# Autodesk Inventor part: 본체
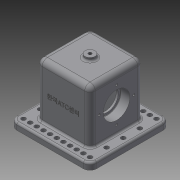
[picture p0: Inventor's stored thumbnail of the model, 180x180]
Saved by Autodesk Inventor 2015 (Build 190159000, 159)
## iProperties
Created: 2018-11
Part Number: 본체
Material: 일반
Document SubType Name: Modeling
Designer: now
Density: 1 g/cm^3
Appearance: 기본값
Author: now
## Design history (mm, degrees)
sketch "스케치1"
  geometry: L1 (-40, 40)-(40, 40); L2 (40, 40)-(40, -40); L3 (40, -40)-(-40, -40); L4 (-40, -40)-(-40, 40); L5 (-40, 40)-(40, -40); L6 (40, 40)-(-40, -40); 1 further point
  constraints: 12 end point, 2 midpoint, 2 parallel, 1 horizontal, 1 perpendicular
  dimensions: "d0" = 80 distance of L2.end L3.end; "d1" = 80 distance of L1.end L2.end
extrude "돌출1" new body sketch "스케치1" distance "d2" = 80; taper "d3" = 0 deg
fillet "모깎기1" dims "d4" = 8
sketch "스케치5"
  geometry: L1 (60, -60)-(-60, -60); L2 (-60, -60)-(-60, 60); L3 (-60, 60)-(60, 60); L4 (60, 60)-(60, -60); L5 (60, -60)-(-60, 60); L6 (-60, -60)-(60, 60); 1 further point
  constraints: 12 end point, 2 midpoint, 2 parallel, 1 horizontal, 1 perpendicular
  dimensions: "d15" = 120 distance of L3.end L1.start; "d16" = 120 distance of L2.end L3.end
extrude "돌출4" join sketch "스케치5" distance "d17" = 10; taper "d18" = 0 deg
sketch "스케치6"
  geometry: L1 (-23, -30)-(23, -30); L2 (23, -30)-(23, 30); L3 (23, 30)-(-23, 30); L4 (-23, 30)-(-23, -30); L5 (-23, -30)-(23, 30); L6 (23, -30)-(-23, 30); 1 further point
  constraints: 12 end point, 2 midpoint, 2 parallel, 1 horizontal, 1 perpendicular
  dimensions: "d19" = 46 distance of L1.start L1.end; "d20" = 60 distance of L1.end L2.end
extrude "돌출5" cut sketch "스케치6" distance "d21" = 80; taper "d22" = 0 deg
sketch "스케치8"
  geometry: L1 (80, 64)-(80, 0) reference; C1 r 16.5 at (42, 32); 2 further points
  constraints: 1 centre point, 1 horizontal alignment, 1 midpoint
  dimensions: "d23" = 33 diameter of C1; "d24" = 38 distance of point (80, 32) C1.centre
extrude "돌출6" cut sketch "스케치8" stored distance "d25" = 10; taper "d26" = 0 deg
sketch "스케치9"
  geometry: C1 r 16.5 at (42, 32) reference; C2 r 20 at (42, 32); 1 further point
  constraints: 1 centre point, 1 coincident
  dimensions: "d27" = 40 diameter of C2
extrude "돌출7" cut sketch "스케치9" distance "d28" = 14; taper "d29" = 0 deg
fillet "모깎기3" dims "d30" = 0.6
sketch "스케치10"
  geometry: L1 (80, 64)-(80, 0) reference; C1 r 20 at (42, 32) reference; 3 further points
  constraints: 1 horizontal alignment, 1 midpoint
  dimensions: "d31" = 26 distance of point (16, 32) C1.centre
hole "구멍1" sketch "스케치10" at (16, 32) diameter "d32" = 3.242; stored, may be unused: countersink angle "d36" = 90 deg, drill point angle "d38" = 118 deg; dims "d33" = 8, "d34" = 4, "d35" = 2, "d37" = 10
fillet "모깎기4" dims "d42" = 10
node "작업 평면2"
sketch "스케치11"
  geometry: C1 r 7.5 at (0, 0); 1 further point
  constraints: 1 centre point, 1 coincident
  dimensions: "d44" = 15 diameter of C1
extrude "돌출8" join sketch "스케치11" stored distance "d45" = 14; taper "d46" = 0 deg
fillet "모깎기5" dims "d47" = 8
sketch "스케치12"
  geometry: C1 r 7.5 at (0, 0) reference
hole "구멍2" sketch "스케치12" at (0, 0) diameter "d48" = 4.917; stored, may be unused: countersink angle "d52" = 90 deg, drill point angle "d54" = 118 deg; dims "d49" = 12, "d50" = 4, "d51" = 2, "d53" = 17.1
sketch "스케치13"
  geometry: C1 r 3.3 at (-50, -50); A1 r 10 centre (-50, -50) between (-60, -50) and (-50, -60) reference; 1 further point
  constraints: 1 centre point, 1 coincident
  dimensions: "d55" = 6.6 diameter of C1
extrude "돌출9" cut sketch "스케치13" stored distance "d56" = 14; taper "d57" = 0 deg
fillet "모깎기6" dims "d64" = 3
fillet "모깎기7" dims "d65" = 3
sketch "스케치14"
  geometry: L1 (92, -82)-(82, -82) reference; 2 further points
  constraints: 1 vertical alignment, 1 other
  dimensions: "d66" = 48 distance from line of L1 point (32, -34)
feature "엠보싱1" sketch "스케치14" dims "d0" = 80, "d1" = 80, "d67" = 0.5, "d68" = 0
fillet "모깎기8" dims "d69" = 3
fillet "모깎기9" dims "d70" = 3
node "솔리드1"
mirror "대칭1"
pattern_circular "원형 패턴1" dims angle "d40" = 360 deg
mirror "대칭2"
pattern_linear "직사각형 패턴1" dims "d60" = 10
mirror "대칭3"
pattern_linear "직사각형 패턴2" dims "d63" = 25
mirror "대칭4"
other parameters: "d43" = -95
